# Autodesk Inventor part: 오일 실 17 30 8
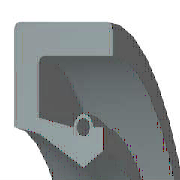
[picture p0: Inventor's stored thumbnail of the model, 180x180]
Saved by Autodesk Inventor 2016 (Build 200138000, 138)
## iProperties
Created: 2012-02
Part Number: 오일 실 17 30 8
Material: 고무
Description: 오일-실
Document SubType Name: Modeling
Standard: KS B 2804
Designer: mduedu
Standards Organization: KS
Language: ko-KR
Size Designation: S - 17 30 8
Categories: <MemberInstance><Categories><Category DisplayName="샤프트 부품" InternalName="7f7aeb1f-a693-4053-b835-cee3144e0d98" Mnemonic="SHFT"><Category DisplayName="실링" Intern
Density: 0.93 g/cm^3
Appearance: 고무 - 검은색 - 버전 1.1
IsCustomPart: 1
Author: mduedu
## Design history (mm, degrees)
revolve "본체" stored, may be unused: angle "d17" = 90 deg
revolve "스프링1" stored, may be unused: angle "d18" = 90 deg
body "Solid1"
sketch "스케치1"
  geometry: L1 (0, 15)-(8, 15); L2 (8, 15)-(8, 13.75); L3 (8, 13.75)-(1.75, 13.75); L4 (0, 15)-(0, 10.6); L5 (0, 10.6)-(1.75, 10.25); L6 (1.75, 10.25)-(4.9, 8.5); L7 (4.9, 8.5)-(0, 8.5); L8 (6.3, 9.375)-(6.3, 10.6); L9 (0, 0)-(9.586, 0) reference; L10 (4.9, 8.5)-(6.3, 9.375); L11 (0, 18)-(0, -3) reference; L12 (-1.917, 0)-(11.503, 0) reference; L13 (4.2, 10.6)-(1.75, 11.09); L14 (1.75, 11.09)-(1.75, 13.75); L15 (6.3, 10.6)-(5.6, 10.6); C1 r 0.455 at (4.9, 10.6); A1 r 0.7 centre (4.9, 10.6) between (5.6, 10.6) and (4.2, 10.6)
  constraints: 26 end point, 5 horizontal alignment, 4 perpendicular, 2 centre point, 2 collinear, 2 horizontal, 2 parallel, 2 point on circle, 2 point on line, 2 vertical alignment, 1 coincident
  dimensions: "d0" = 30 diameter of L1 L9 (= SD2); "d1" = 18.75 diameter of L8.start L9 (= ABDM); "d2" = 1.25 distance of L1.end L2.end (computed from SD); "d3" = 0.91 diameter of C1 (= SPDI); "d4" = 1.4 diameter of A1 (= SPDA); "d5" = 17 diameter of L6.end L9 (= NND); "d6" = 20.5 diameter of L5.end L9 (= TKDM); "d7" = 21.2 diameter of L4.end L9 (= HLDM); "d8" = 4.9 distance from line of C1.centre L4 (= SPDST); "d9" = 6.3 distance between parallel lines of L8 L4 (= SDI); "d10" = 8 distance between parallel lines of L2 L4 (= SWDT); "d12" = 1.75 distance between parallel lines of L14 L4 (= SD)
fillet "모깎기1" dims "d11" = 0.3 (= RR)
other parameters: "SD2" = 30 [user parameter; used in 1 equation term], "SWDT" = 8 [user parameter; used in 1 equation term], "RR" = 0.3 [user parameter; used in 1 equation term], "SD" = 1.75 [user parameter; used in 2 equation terms], "NND" = 17 [user parameter; used in 1 equation term], "SPDA" = 1.4 [user parameter; used in 1 equation term], "SPDI" = 0.91 [user parameter; used in 1 equation term], "TKDM" = 20.5 [user parameter; used in 1 equation term], "HLDM" = 21.2 [user parameter; used in 1 equation term], "ABDM" = 18.75 [user parameter; used in 1 equation term], "SDI" = 6.3 [user parameter; used in 1 equation term], "SPDST" = 4.9 [user parameter; used in 1 equation term], "d13" = 0, "d14" = 0, "d15" = 0, "LAB" = 0.35 [user parameter]
